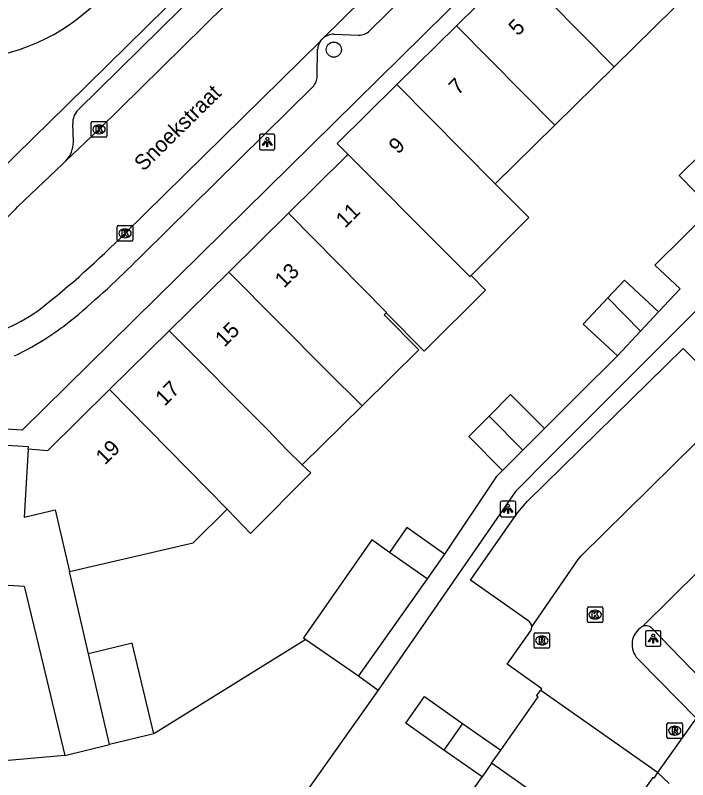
# Model space of a CAD drawing. Extents: x 160107 to 160928, y 382056 to 382918.
# Drawn here: x 160601.98 to 160645.36, y 382585.29 to 382634.56 of the extents above; entities that cross this region are included whole.
import ezdxf

# ---------------------------------------------------------------- set-up
doc = ezdxf.new("R2010")
doc.units = 0
for name, color, linetype in [('IMGEO_Boom', 7, 'Continuous'), ('IMGEO_Kolk', 7, 'Continuous'), ('IMGEO_Lichtpunt', 7, 'Continuous'), ('IMGEO_Openbare_ruimte_label', 7, 'Continuous'), ('IMGEO_Pand', 7, 'Continuous'), ('IMGEO_Pand_nummerreeks', 7, 'Continuous'), ('IMGEO_Parkeervlak_open', 7, 'Continuous'), ('IMGEO_Rijbaan_lokaal_open', 7, 'Continuous'), ('IMGEO_Rioolput', 7, 'Continuous'), ('IMGEO_Voetpad_open', 7, 'Continuous')]:
    doc.layers.add(name, color=color, linetype=linetype)

msp = doc.modelspace()

# ---------------------------------------------------------------- linework, layer by layer
at = {"layer": 'IMGEO_Boom'}
msp.add_circle((160622.528, 382632.346), 0.489, dxfattribs=at)
at = {"layer": 'IMGEO_Kolk'}
for p, q in [((160606.882, 382626.78), (160606.882, 382627.632)), ((160606.957, 382627.706), (160607.809, 382627.706)), ((160607.883, 382627.632), (160607.883, 382626.78)), ((160607.37, 382627.486), (160607.395, 382627.486)), ((160607.809, 382626.706), (160606.957, 382626.706)), ((160607.393, 382626.926), (160607.368, 382626.926)), ((160608.56, 382620.076), (160608.56, 382620.928)), ((160608.635, 382621.002), (160609.487, 382621.002)), ((160609.048, 382620.782), (160609.073, 382620.782)), ((160609.561, 382620.928), (160609.561, 382620.076)), ((160609.071, 382620.222), (160609.046, 382620.222)), ((160609.487, 382620.002), (160608.635, 382620.002)), ((160638.882, 382595.502), (160638.882, 382596.354)), ((160638.957, 382596.428), (160639.809, 382596.428)), ((160639.37, 382596.208), (160639.395, 382596.208)), ((160639.883, 382596.354), (160639.883, 382595.502)), ((160639.393, 382595.648), (160639.368, 382595.648)), ((160639.809, 382595.428), (160638.957, 382595.428))]:
    msp.add_line(p, q, dxfattribs=at)
for points in [[(160606.882, 382626.78), (160606.882, 382627.632)], [(160606.957, 382627.706), (160607.809, 382627.706)], [(160607.883, 382627.632), (160607.883, 382626.78)], [(160607.203, 382627.406), (160607.326, 382627.406), (160607.326, 382627.255), (160607.456, 382627.406), (160607.62, 382627.406), (160607.474, 382627.255), (160607.627, 382627.006), (160607.475, 382627.006), (160607.39, 382627.17), (160607.326, 382627.103), (160607.326, 382627.006), (160607.203, 382627.006), (160607.203, 382627.406)], [(160607.809, 382626.706), (160606.957, 382626.706)], [(160608.56, 382620.076), (160608.56, 382620.928)], [(160608.635, 382621.002), (160609.487, 382621.002)], [(160608.881, 382620.702), (160609.004, 382620.702), (160609.004, 382620.551), (160609.134, 382620.702), (160609.298, 382620.702), (160609.152, 382620.551), (160609.305, 382620.302), (160609.153, 382620.302), (160609.068, 382620.466), (160609.004, 382620.399), (160609.004, 382620.302), (160608.881, 382620.302), (160608.881, 382620.702)], [(160609.561, 382620.928), (160609.561, 382620.076)], [(160609.487, 382620.002), (160608.635, 382620.002)], [(160638.882, 382595.502), (160638.882, 382596.354)], [(160638.957, 382596.428), (160639.809, 382596.428)], [(160639.203, 382596.128), (160639.326, 382596.128), (160639.326, 382595.977), (160639.456, 382596.128), (160639.62, 382596.128), (160639.474, 382595.977), (160639.627, 382595.728), (160639.475, 382595.728), (160639.39, 382595.892), (160639.326, 382595.825), (160639.326, 382595.728), (160639.203, 382595.728), (160639.203, 382596.128)], [(160639.883, 382596.354), (160639.883, 382595.502)], [(160639.809, 382595.428), (160638.957, 382595.428)]]:
    msp.add_lwpolyline(points, dxfattribs=at)
for centre, start, end in [((160606.959, 382627.63), 91.552, 178.448), ((160606.959, 382627.63), 91.552, 178.448), ((160607.807, 382627.63), 1.552, 88.448), ((160607.807, 382627.63), 1.552, 88.448), ((160606.959, 382626.782), 181.552, 268.448), ((160606.959, 382626.782), 181.552, 268.448), ((160607.807, 382626.782), 271.552, 358.448), ((160607.807, 382626.782), 271.552, 358.448), ((160608.637, 382620.926), 91.552, 178.448), ((160608.637, 382620.926), 91.552, 178.448), ((160609.485, 382620.926), 1.552, 88.448), ((160609.485, 382620.926), 1.552, 88.448), ((160608.637, 382620.078), 181.552, 268.448), ((160608.637, 382620.078), 181.552, 268.448), ((160609.485, 382620.078), 271.552, 358.448), ((160609.485, 382620.078), 271.552, 358.448), ((160638.959, 382596.352), 91.552, 178.448), ((160638.959, 382596.352), 91.552, 178.448), ((160639.807, 382596.352), 1.552, 88.448), ((160639.807, 382596.352), 1.552, 88.448), ((160638.959, 382595.504), 181.552, 268.448), ((160638.959, 382595.504), 181.552, 268.448), ((160639.807, 382595.504), 271.552, 358.448), ((160639.807, 382595.504), 271.552, 358.448)]:
    msp.add_arc(centre, 0.0765, start, end, dxfattribs=at)
for centre, major_axis, ratio, start_param, end_param in [((160607.369, 382627.206), (-0.387, 0.002), 0.722429, 4.712389, 7.853982), ((160607.394, 382627.206), (-0.39, 0.002), 0.717154, 1.570796, 4.712389), ((160609.047, 382620.502), (-0.387, 0.002), 0.722429, 4.712389, 7.853982), ((160609.072, 382620.502), (-0.39, 0.002), 0.717154, 1.570796, 4.712389), ((160639.369, 382595.928), (-0.387, 0.002), 0.722429, 4.712389, 7.853982), ((160639.394, 382595.928), (-0.39, 0.002), 0.717154, 1.570796, 4.712389)]:
    msp.add_ellipse(centre, major_axis=major_axis, ratio=ratio, start_param=start_param, end_param=end_param, dxfattribs=at)
at = {"layer": 'IMGEO_Lichtpunt'}
for p, q in [((160617.737, 382626.797), (160617.737, 382625.99)), ((160617.737, 382626.797), (160617.737, 382625.99)), ((160618.639, 382626.892), (160617.831, 382626.892)), ((160618.639, 382626.892), (160617.831, 382626.892)), ((160618.733, 382625.99), (160618.733, 382626.797)), ((160618.733, 382625.99), (160618.733, 382626.797)), ((160617.831, 382625.896), (160618.639, 382625.896)), ((160617.831, 382625.896), (160618.639, 382625.896)), ((160633.268, 382603.143), (160633.268, 382602.336)), ((160633.268, 382603.143), (160633.268, 382602.336)), ((160634.17, 382603.238), (160633.362, 382603.238)), ((160634.17, 382603.238), (160633.362, 382603.238)), ((160634.264, 382602.336), (160634.264, 382603.143)), ((160634.264, 382602.336), (160634.264, 382603.143)), ((160633.362, 382602.242), (160634.17, 382602.242)), ((160633.362, 382602.242), (160634.17, 382602.242)), ((160642.633, 382594.788), (160642.633, 382593.981)), ((160642.633, 382594.788), (160642.633, 382593.981)), ((160643.535, 382594.883), (160642.727, 382594.883)), ((160643.535, 382594.883), (160642.727, 382594.883)), ((160643.629, 382593.981), (160643.629, 382594.788)), ((160643.629, 382593.981), (160643.629, 382594.788)), ((160642.727, 382593.887), (160643.535, 382593.887)), ((160642.727, 382593.887), (160643.535, 382593.887))]:
    msp.add_line(p, q, dxfattribs=at)
for points in [[(160618.111, 382626.461), (160618.15, 382626.433), (160617.962, 382626.171), (160617.924, 382626.198), (160618.111, 382626.461)], [(160618.213, 382626.413), (160618.26, 382626.413), (160618.26, 382626.091), (160618.213, 382626.091), (160618.213, 382626.413)], [(160618.323, 382626.433), (160618.361, 382626.46), (160618.548, 382626.198), (160618.509, 382626.17), (160618.323, 382626.433)], [(160633.642, 382602.807), (160633.681, 382602.779), (160633.493, 382602.517), (160633.455, 382602.544), (160633.642, 382602.807)], [(160633.744, 382602.759), (160633.791, 382602.759), (160633.791, 382602.437), (160633.744, 382602.437), (160633.744, 382602.759)], [(160633.854, 382602.779), (160633.892, 382602.806), (160634.079, 382602.544), (160634.04, 382602.516), (160633.854, 382602.779)], [(160643.007, 382594.452), (160643.046, 382594.424), (160642.858, 382594.162), (160642.82, 382594.189), (160643.007, 382594.452)], [(160643.109, 382594.404), (160643.156, 382594.404), (160643.156, 382594.082), (160643.109, 382594.082), (160643.109, 382594.404)], [(160643.219, 382594.424), (160643.257, 382594.451), (160643.444, 382594.189), (160643.405, 382594.161), (160643.219, 382594.424)]]:
    msp.add_lwpolyline(points, dxfattribs=at)
for centre in [(160618.236, 382626.595), (160633.767, 382602.941), (160643.132, 382594.586)]:
    msp.add_circle(centre, 0.0994, dxfattribs=at)
for centre, start, end in [((160617.831, 382626.797), 90, 180), ((160617.831, 382626.797), 90, 180), ((160618.639, 382626.797), 0, 90), ((160618.639, 382626.797), 0, 90), ((160617.831, 382625.99), 180, 270), ((160617.831, 382625.99), 180, 270), ((160618.639, 382625.99), 270, 0), ((160618.639, 382625.99), 270, 360), ((160633.362, 382603.143), 90, 180), ((160633.362, 382603.143), 90, 180), ((160634.17, 382603.143), 0, 90), ((160634.17, 382603.143), 0, 90), ((160633.362, 382602.336), 180, 270), ((160633.362, 382602.336), 180, 270), ((160634.17, 382602.336), 270, 0), ((160634.17, 382602.336), 270, 360), ((160642.727, 382594.788), 90, 180), ((160642.727, 382594.788), 90, 180), ((160643.535, 382594.788), 0, 90), ((160643.535, 382594.788), 0, 90), ((160642.727, 382593.981), 180, 270), ((160642.727, 382593.981), 180, 270), ((160643.535, 382593.981), 270, 0), ((160643.535, 382593.981), 270, 360)]:
    msp.add_arc(centre, 0.0946, start, end, dxfattribs=at)
at = {"layer": 'IMGEO_Pand'}
for points in [[(160634.268, 382637.664), (160630.432, 382633.883)], [(160634.268, 382637.664), (160640.62, 382631.244)], [(160640.62, 382631.244), (160644.465, 382635.025)], [(160630.432, 382633.883), (160626.598, 382630.102)], [(160630.432, 382633.883), (160636.792, 382627.478)], [(160636.792, 382627.478), (160640.62, 382631.244)], [(160626.598, 382630.102), (160622.74, 382626.3), (160623.44, 382625.598)], [(160632.941, 382623.689), (160626.598, 382630.102)], [(160632.941, 382623.689), (160636.792, 382627.478)], [(160623.44, 382625.598), (160623.314, 382625.474), (160619.597, 382621.808)], [(160631.378, 382617.789), (160631.311, 382617.722), (160629.798, 382619.222), (160623.44, 382625.598)], [(160646.204, 382625.6), (160644.812, 382624.225), (160646.911, 382622.082)], [(160631.378, 382617.789), (160635.111, 382621.515), (160632.941, 382623.689)], [(160619.597, 382621.808), (160615.748, 382618.012)], [(160619.597, 382621.808), (160625.931, 382615.409), (160625.913, 382615.391)], [(160615.748, 382618.012), (160611.91, 382614.226)], [(160615.748, 382618.012), (160622.09, 382611.63), (160624.353, 382609.396)], [(160625.913, 382615.391), (160628.352, 382612.917), (160632.322, 382616.832), (160631.378, 382617.789)], [(160643.473, 382615.438), (160641.276, 382617.494), (160640.202, 382616.347)], [(160640.202, 382616.347), (160638.622, 382614.659), (160640.819, 382612.603)], [(160640.202, 382616.347), (160642.32, 382614.206)], [(160624.353, 382609.396), (160628.007, 382612.999), (160625.778, 382615.258), (160625.913, 382615.391)], [(160642.32, 382614.206), (160643.473, 382615.438)], [(160611.91, 382614.226), (160608.062, 382610.431)], [(160611.91, 382614.226), (160618.26, 382607.86), (160619.515, 382606.532), (160620.497, 382605.592)], [(160642.32, 382614.206), (160640.819, 382612.603)], [(160608.062, 382610.431), (160604.055, 382606.479), (160602.819, 382606.589)], [(160615.651, 382602.72), (160608.062, 382610.431)], [(160636.116, 382607.928), (160633.931, 382610.113), (160632.545, 382608.727)], [(160620.497, 382605.592), (160624.353, 382609.396)], [(160632.545, 382608.727), (160631.232, 382607.414), (160633.417, 382605.229)], [(160632.545, 382608.727), (160634.719, 382606.531)], [(160636.116, 382607.928), (160634.719, 382606.531)], [(160602.819, 382606.589), (160602.83, 382606.749), (160597.253, 382607.097)], [(160602.819, 382606.589), (160602.55, 382602.22), (160604.55, 382602.68), (160605.472, 382598.707)], [(160634.719, 382606.531), (160633.417, 382605.229)], [(160615.651, 382602.72), (160617.148, 382601.168), (160621.048, 382605.065), (160620.497, 382605.592)], [(160605.472, 382598.707), (160613.462, 382600.561), (160615.651, 382602.72)], [(160629.658, 382599.829), (160627.242, 382601.535), (160626.129, 382599.941)], [(160626.129, 382599.941), (160624.983, 382600.748), (160620.577, 382594.436), (160620.731, 382594.33)], [(160628.539, 382598.244), (160626.129, 382599.941)], [(160629.658, 382599.829), (160628.539, 382598.244)], [(160606.704, 382593.401), (160605.472, 382598.707)], [(160596.681, 382598.12), (160602.211, 382597.779), (160602.544, 382597.758), (160603.77, 382592.691), (160605.181, 382586.859)], [(160628.539, 382598.244), (160624.125, 382591.993)], [(160610.924, 382588.248), (160609.514, 382594.08), (160606.704, 382593.401)], [(160620.731, 382594.33), (160624.125, 382591.993)], [(160608.061, 382587.556), (160606.704, 382593.401)], [(160633.296, 382587.194), (160635.7, 382590.62), (160635.609, 382590.684), (160635.865, 382591.048), (160635.872, 382591.043)], [(160629.633, 382587.199), (160627.176, 382588.922), (160628.382, 382590.641), (160630.839, 382588.918)], [(160643.411, 382585.751), (160635.872, 382591.043)], [(160630.839, 382588.918), (160629.633, 382587.199)], [(160630.839, 382588.918), (160633.296, 382587.194)], [(160610.924, 382588.248), (160608.061, 382587.556)], [(160605.181, 382586.859), (160608.061, 382587.556)], [(160632.091, 382585.475), (160629.633, 382587.199)], [(160632.709, 382586.356), (160633.296, 382587.194)], [(160632.709, 382586.356), (160632.091, 382585.475)], [(160640.182, 382581.087), (160632.709, 382586.356)], [(160643.411, 382585.751), (160643.165, 382585.386), (160643.099, 382585.431), (160640.19, 382581.289), (160640.28, 382581.226), (160640.182, 382581.087)], [(160629.508, 382581.985), (160629.6, 382582.116), (160629.69, 382582.053), (160632.091, 382585.475)]]:
    msp.add_lwpolyline(points, dxfattribs=at)
at = {"layer": 'IMGEO_Parkeervlak_open'}
for points in [[(160635.049, 382595.543), (160631.335, 382598.143), (160634.382, 382602.498), (160635.031, 382603.243), (160645.054, 382613.091), (160648.148, 382609.999)], [(160643.018, 382595.08), (160646.201, 382591.793)]]:
    msp.add_lwpolyline(points, dxfattribs=at)
for centre, radius, start, end in [((160634.823, 382595.127), 0.474, 2.3141, 61.4629), ((160642.666, 382594.668), 0.542, 49.5154, 114.9983)]:
    msp.add_arc(centre, radius, start, end, dxfattribs=at)
at = {"layer": 'IMGEO_Rijbaan_lokaal_open'}
for points in [[(160635.901, 382655.273), (160607.381, 382627.202), (160605.252, 382625.176)], [(160621.788, 382633.043), (160640.083, 382651.015)], [(160621.652, 382632.878), (160621.788, 382633.043)], [(160609.063, 382620.506), (160621.652, 382632.878)], [(160602.149, 382622.229), (160605.057, 382624.991), (160605.252, 382625.176)], [(160635.296, 382595.146), (160638.293, 382599.479), (160638.478, 382599.711), (160648.818, 382609.892)], [(160653.567, 382606.153), (160642.437, 382595.159)], [(160635.872, 382591.043), (160635.948, 382591.15), (160633.717, 382592.731), (160635.252, 382594.928)], [(160620.731, 382594.33), (160610.924, 382588.248)], [(160645.905, 382589.254), (160642.247, 382592.972)], [(160624.125, 382591.993), (160625.392, 382591.063)], [(160625.392, 382591.063), (160615.956, 382577.738)], [(160645.905, 382589.254), (160643.411, 382585.751)], [(160605.181, 382586.859), (160597.864, 382586.195)], [(160644.153, 382585.048), (160643.411, 382585.751)]]:
    msp.add_lwpolyline(points, dxfattribs=at)
for centre, radius, start, end in [((160595.308, 382628.348), 9.178, 296.6776, 318.1863), ((160566.603, 382662.625), 59.807, 308.23031, 315.23093), ((160596.488, 382625.35), 12.04, 283.4844, 306.2862), ((160634.826, 382595.127), 0.47, 334.9106, 2.2674), ((160643.094, 382593.998), 1.33, 127.6184, 230.4526), ((160642.664, 382594.668), 0.541, 114.8052, 134.9304)]:
    msp.add_arc(centre, radius, start, end, dxfattribs=at)
at = {"layer": 'IMGEO_Rioolput'}
for p, q in [((160635.446, 382593.836), (160635.446, 382594.688)), ((160635.521, 382594.762), (160636.373, 382594.762)), ((160635.934, 382594.542), (160635.959, 382594.542)), ((160636.447, 382594.688), (160636.447, 382593.836)), ((160636.373, 382593.762), (160635.521, 382593.762)), ((160635.957, 382593.982), (160635.932, 382593.982)), ((160644.019, 382588.023), (160644.019, 382588.875)), ((160644.094, 382588.949), (160644.946, 382588.949)), ((160644.507, 382588.729), (160644.532, 382588.729)), ((160645.02, 382588.875), (160645.02, 382588.023)), ((160644.53, 382588.169), (160644.505, 382588.169)), ((160644.946, 382587.949), (160644.094, 382587.949))]:
    msp.add_line(p, q, dxfattribs=at)
for points in [[(160635.446, 382593.836), (160635.446, 382594.688)], [(160635.521, 382594.762), (160636.373, 382594.762)], [(160636.447, 382594.688), (160636.447, 382593.836)], [(160636.035, 382594.46), (160635.783, 382594.462), (160635.783, 382594.062)], [(160635.783, 382594.062), (160635.907, 382594.062), (160635.907, 382594.224), (160635.918, 382594.224)], [(160635.961, 382594.381), (160635.907, 382594.381), (160635.907, 382594.3)], [(160635.907, 382594.3), (160635.959, 382594.3)], [(160635.965, 382594.195), (160636.036, 382594.062), (160636.176, 382594.062), (160636.111, 382594.188)], [(160636.373, 382593.762), (160635.521, 382593.762)], [(160644.019, 382588.023), (160644.019, 382588.875)], [(160644.094, 382588.949), (160644.946, 382588.949)], [(160644.608, 382588.647), (160644.356, 382588.649), (160644.356, 382588.249)], [(160645.02, 382588.875), (160645.02, 382588.023)], [(160644.356, 382588.249), (160644.48, 382588.249), (160644.48, 382588.411), (160644.491, 382588.411)], [(160644.534, 382588.568), (160644.48, 382588.568), (160644.48, 382588.487)], [(160644.48, 382588.487), (160644.532, 382588.487)], [(160644.538, 382588.382), (160644.609, 382588.249), (160644.749, 382588.249), (160644.684, 382588.375)], [(160644.946, 382587.949), (160644.094, 382587.949)]]:
    msp.add_lwpolyline(points, dxfattribs=at)
for centre, radius, start, end in [((160635.523, 382594.686), 0.0765, 91.552, 178.448), ((160635.523, 382594.686), 0.0765, 91.552, 178.448), ((160636.371, 382594.686), 0.0765, 1.552, 88.448), ((160636.371, 382594.686), 0.0765, 1.552, 88.448), ((160635.917, 382594.171), 0.0533, 26.0293, 88.6989), ((160635.943, 382594.489), 0.19, 274.7715, 282.9687), ((160635.967, 382594.285), 0.0964, 77.0061, 93.1865), ((160635.981, 382594.342), 0.0378, 276.6634, 79.6772), ((160636.034, 382594.35), 0.109, 350.3612, 89.416), ((160636.032, 382594.35), 0.112, 277.5842, 350.9817), ((160636.016, 382594.135), 0.108, 29.5134, 73.7905), ((160635.523, 382593.838), 0.0765, 181.552, 268.448), ((160635.523, 382593.838), 0.0765, 181.552, 268.448), ((160636.371, 382593.838), 0.0765, 271.552, 358.448), ((160636.371, 382593.838), 0.0765, 271.552, 358.448), ((160644.096, 382588.873), 0.0765, 91.552, 178.448), ((160644.096, 382588.873), 0.0765, 91.552, 178.448), ((160644.607, 382588.537), 0.109, 350.3612, 89.416), ((160644.944, 382588.873), 0.0765, 1.552, 88.448), ((160644.944, 382588.873), 0.0765, 1.552, 88.448), ((160644.49, 382588.358), 0.0533, 26.0293, 88.6989), ((160644.516, 382588.676), 0.19, 274.7715, 282.9687), ((160644.54, 382588.472), 0.0964, 77.0061, 93.1865), ((160644.554, 382588.529), 0.0378, 276.6634, 79.6772), ((160644.605, 382588.537), 0.112, 277.5842, 350.9817), ((160644.589, 382588.322), 0.108, 29.5134, 73.7905), ((160644.096, 382588.025), 0.0765, 181.552, 268.448), ((160644.096, 382588.025), 0.0765, 181.552, 268.448), ((160644.944, 382588.025), 0.0765, 271.552, 358.448), ((160644.944, 382588.025), 0.0765, 271.552, 358.448)]:
    msp.add_arc(centre, radius, start, end, dxfattribs=at)
for centre, major_axis, ratio, start_param, end_param in [((160635.933, 382594.262), (-0.387, 0.002), 0.722429, 4.712389, 7.853982), ((160635.958, 382594.262), (-0.39, 0.002), 0.717154, 1.570796, 4.712389), ((160644.506, 382588.449), (-0.387, 0.002), 0.722429, 4.712389, 7.853982), ((160644.531, 382588.449), (-0.39, 0.002), 0.717154, 1.570796, 4.712389)]:
    msp.add_ellipse(centre, major_axis=major_axis, ratio=ratio, start_param=start_param, end_param=end_param, dxfattribs=at)
at = {"layer": 'IMGEO_Voetpad_open'}
for points in [[(160606.041, 382628.472), (160633.864, 382655.834)], [(160646.97, 382651.686), (160602.42, 382607.815), (160569.084, 382609.884)], [(160624.837, 382633.553), (160642.731, 382651.127)], [(160619.427, 382642.677), (160605.335, 382628.789), (160599.766, 382623.349)], [(160622.542, 382633.334), (160624.13, 382633.278)], [(160621.461, 382630.634), (160621.486, 382632.366)], [(160610.2, 382619.138), (160621.168, 382629.948)], [(160605.736, 382626.395), (160605.686, 382627.559)], [(160646.911, 382622.082), (160643.224, 382618.455), (160644.862, 382616.922), (160643.473, 382615.438)], [(160707.98, 382577.092), (160700.613, 382568.641), (160695.239, 382572.24), (160691.681, 382569.709), (160646.145, 382615.771), (160636.494, 382606.115), (160634.251, 382603.871), (160625.392, 382591.063)], [(160640.819, 382612.603), (160638.315, 382610.127), (160636.116, 382607.928)], [(160633.417, 382605.229), (160633.006, 382604.818), (160629.658, 382599.829)]]:
    msp.add_lwpolyline(points, dxfattribs=at)
for centre, radius, start, end in [((160598.31, 382644.385), 12.652, 263.9378, 350.1374), ((160624.163, 382634.24), 0.962, 268.0425, 314.4663), ((160622.508, 382632.3), 1.035, 88.1159, 134.0915), ((160622.491, 382632.323), 1.005, 146.5109, 177.5618), ((160620.489, 382630.644), 0.972, 314.3141, 359.4299), ((160606.885, 382627.618), 1.2, 134.6735, 182.8316), ((160603.865, 382626.432), 1.871, 317.8291, 358.8602), ((160563.564, 382665.202), 65.55, 310.42968, 315.35369), ((160593.932, 382629.434), 18.629, 295.403, 310.6739)]:
    msp.add_arc(centre, radius, start, end, dxfattribs=at)

# ---------------------------------------------------------------- texts
at = {"layer": 'IMGEO_Openbare_ruimte_label'}
msp.add_text('Snoekstraat', height=1, rotation=44.5138, dxfattribs=at).set_placement((160610.248, 382624.456))
at = {"layer": 'IMGEO_Pand_nummerreeks'}
for s, rotation, p in [('5', 44.591, (160634.396, 382633.184)), ('7', 44.591, (160630.531, 382629.373)), ('9', 44.5933, (160626.665, 382625.562)), ('11', 44.6048, (160623.25, 382620.803)), ('13', 44.6048, (160619.316, 382616.924)), ('15', 44.6046, (160615.464, 382613.125)), ('17', 44.6048, (160611.612, 382609.326)), ('19', 44.6046, (160607.76, 382605.527))]:
    msp.add_text(s, height=1, rotation=rotation, dxfattribs=at).set_placement(p)

doc.saveas('drawing.dxf')
